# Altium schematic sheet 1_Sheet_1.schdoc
size 215 x 152 mm; Name: A_Customize; Symbol: A_Customize; Device: A_Customize; @Project Name: Sheet_1; REV: 1.0; Date: 2024-01-03; Sheet: 1/1; Company: Your Company; Convert to PCB: yes; Add into BOM: yes; spicePre: .
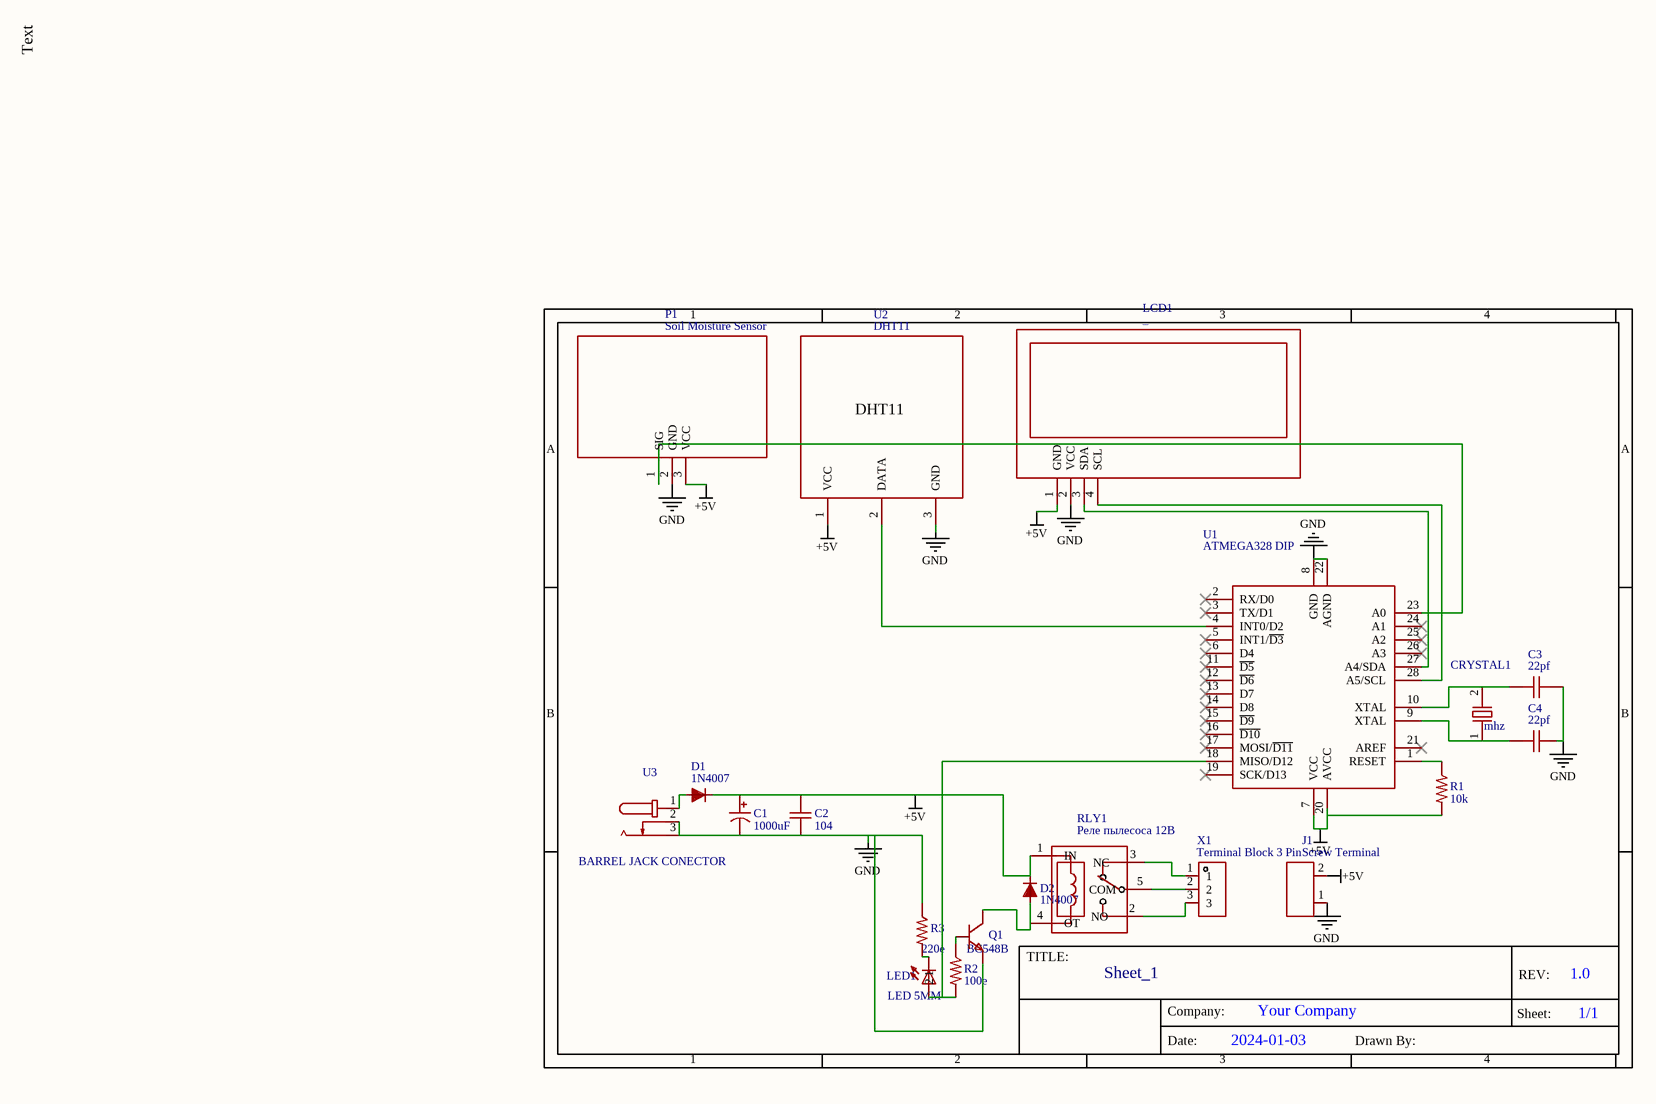
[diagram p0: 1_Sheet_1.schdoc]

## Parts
C1  1000uF  [CAP1000UFX25V-10X20(5MM, D-0.8)]
C2  104  [NP CAP-8*3.5-5.08MM]
C3  22pf  [CAP-TH_L5.0-W2.5-P2.54-D0.7]
C4  22pf  [CAP-TH_L5.0-W2.5-P2.54-D0.7]
CRYSTAL1  mhz  [CRYSTAL-TH_L10.8-W4.5-P4.88]
D1  1N4007  [1N4007]
D2  1N4007  [1N4007]
J1  Screw Terminal  [H2-5.0-10.5X8.0MM]
LCD1  _  [FP LCDI2C]
LED1  LED 5MM  [LED-5MM-5MM]
P1  Soil Moisture Sensor  [SOIL MOISTURE SENSOR]
Q1  BC548B
R1  10k  [RESISTOR-1/4W]
R2  100e  [RESISTOR-1/4W]
R3  220e  [RESISTOR-1/4W]
RLY1  Реле пылесоса 12В  [RELAY-TH_SRD-XXVDC-XL-C]
U1  ATMEGA328 DIP  [ATMEGA328P]
U2  DHT11  [DHT11]
U3  BARREL JACK CONECTOR  [BARREL JACK_FOOTPRINT]
X1  Terminal Block 3 Pin

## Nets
+5V: C1.1 C2.2 D1.K D2.K J1.2 LCD1.1(GND) P1.3(VCC) R1.2 RLY1.1(IN) U1.7(VCC) U1.20(AVCC) U2.1(VCC)
GND: C1.2 C2.1 C3.1 C4.1 J1.1 LCD1.2(VCC) P1.2(GND) Q1.3(E) R3.1 U1.8(GND) U1.22(AGND) U2.3(GND) U3.2 U3.3
NetC3_2: C3.2 CRYSTAL1.2 U1.10(XTAL)
NetC4_2: C4.2 CRYSTAL1.1 U1.9(XTAL)
NetD1_A: D1.A U3.1
NetD2_A: D2.A Q1.1(C) RLY1.4(OT)
NetLCD1_3: LCD1.3(SDA) U1.27(A4/SDA)
NetLCD1_4: LCD1.4(SCL) U1.28(A5/SCL)
NetLED1_1: LED1.1 R2.2 U1.18(MISO/D12)
NetLED1_2: LED1.2 R3.2
NetP1_1: P1.1(SIG) U1.23(A0)
NetQ1_2: Q1.2(B) R2.1
NetR1_1: R1.1 U1.1(RESET)
NetRLY1_2: RLY1.2(NO) X1.3
NetRLY1_3: RLY1.3(NC) X1.1
NetRLY1_5: RLY1.5(COM) X1.2
NetU1_4: U1.4(INT0/D2) U2.2(DATA)

Not connected (* = marked no-connect by the designer): U1 2(RX/D0)* 3(TX/D1)* 5(INT1/~{D3})* 6(D4)* 11(~{D5})* 12(~{D6})* 13(D7)* 14(D8)* 15(~{D9})* 16(~{D10})* 17(MOSI/~{D11})* 19(SCK/D13)* 21(AREF)* 24(A1)* 25(A2)* 26(A3)*

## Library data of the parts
C1 = 1000uF: Manufacturer: Rubycon; Manufacturer Part: 16ZLH680MEFC8X16; Voltage: 25V; Convert to PCB: yes
C2 = 104: Manufacturer: ReliaPro; Manufacturer Part: Suppression Capacitor222M/250V; Convert to PCB: yes; nameAlias: Value; Contributor: sunbin
C3 C4 = 22pf: Manufacturer: Dersonic(德尔创); Manufacturer Part: CC1H103ZA1AD3F4D10MF; Convert to PCB: yes; nameAlias: Value; Contributor: LCSC
CRYSTAL1 = mhz: Manufacturer: HUAXIN(华昕); Manufacturer Part: SP2005M52920001; Convert to PCB: yes; nameAlias: Value; Contributor: lcsc
D1 D2 = 1N4007: Convert to PCB: yes; Contributor: Ryan Baga
J1 = Screw Terminal: Convert to PCB: yes
LCD1 = _: Convert to PCB: yes; Contributor: chiragkhumane
LED1 = LED 5MM: Convert to PCB: yes; Contributor: justin123574
P1 = Soil Moisture Sensor: Convert to PCB: yes; sourceId: i6oizRL3l
Q1 = BC548B: Manufacturer: CJ(江苏长电/长晶); Manufacturer Part: BC548; Convert to PCB: yes; Origin Footprint: TO-92-3_L4.9-W3.7-P1.27-L
R1 = 10k: Convert to PCB: yes; Contributor: Essam12 M
R2 = 100e: Convert to PCB: yes; Contributor: Essam12 M
R3 = 220e: Convert to PCB: yes; Contributor: Essam12 M
RLY1 = Реле пылесоса 12В: Manufacturer: 松乐; Manufacturer Part: SRD-24VDC-SL-C; Value: Relay; Convert to PCB: yes; Contributor: Павел Майоров
U1 = ATMEGA328 DIP: Convert to PCB: yes; Contributor: electromaniax
U2 = DHT11: Convert to PCB: yes; Contributor: guangyang256
U3 = BARREL JACK CONECTOR: Convert to PCB: yes; Contributor: piluf
X1 = Terminal Block 3 Pin: Convert to PCB: yes; Origin Footprint: TERMINAL BLOCK SCREW 3; Contributor: educasgodson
